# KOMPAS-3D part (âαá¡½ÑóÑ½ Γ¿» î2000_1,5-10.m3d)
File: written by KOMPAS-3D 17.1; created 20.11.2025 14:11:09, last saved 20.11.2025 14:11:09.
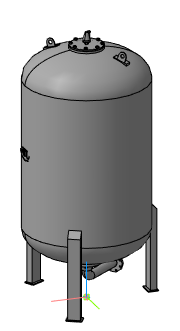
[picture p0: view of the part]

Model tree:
1. Операция без истории:1

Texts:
  REVIT MATERIAL OVERRIDDEN
  REVIT MATERIAL ID
  REVIT SUBCATEGORY ID
  REVIT CATEGORY ID
  REVIT ELEMENT ID
  REVIT BREP TAG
